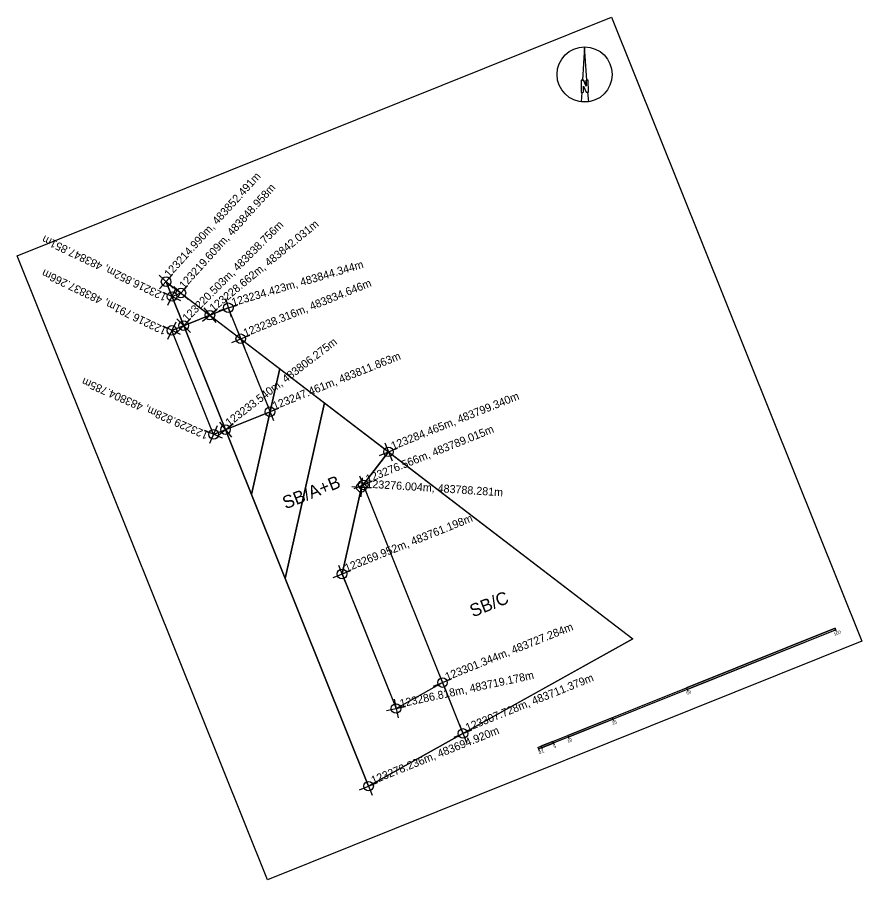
# Model space of a CAD drawing. Extents: x 123168 to 123432, y 483666 to 483935.
import ezdxf

# ---------------------------------------------------------------- set-up
doc = ezdxf.new("R2010")
doc.units = 0
for name, color, linetype in [('# coördinaten geheel', 7, 'Continuous'), ('# hulplijn', 7, 'Continuous'), ('Default', 7, 'Continuous')]:
    doc.layers.add(name, color=color, linetype=linetype)

msp = doc.modelspace()

# ---------------------------------------------------------------- linework, layer by layer
at = {"layer": '# coördinaten geheel'}
for p, q in [((123345.34, 483915.42), (123344.64, 483915.41)), ((123344.64, 483915.41), (123344.68, 483911.62)), ((123346.21, 483913.6), (123345.34, 483915.42)), ((123346.89, 483915.44), (123346.19, 483915.43)), ((123346.19, 483915.43), (123346.21, 483913.6)), ((123346.93, 483911.64), (123346.89, 483915.44)), ((123345.38, 483911.63), (123345.36, 483913.59)), ((123345.36, 483913.59), (123346.23, 483911.64)), ((123344.68, 483911.62), (123345.38, 483911.63)), ((123346.23, 483911.64), (123346.93, 483911.64)), ((123212.77, 483854.51), (123217.21, 483850.47)), ((123212.97, 483850.27), (123217.01, 483854.71)), ((123217.39, 483850.97), (123221.83, 483846.94)), ((123217.59, 483846.74), (123221.63, 483851.18)), ((123219.56, 483846.55), (123214.15, 483849.15)), ((123215.55, 483845.15), (123218.15, 483850.55)), ((123233.58, 483847.22), (123235.27, 483841.47)), ((123226.34, 483840.13), (123230.98, 483843.93)), ((123226.76, 483844.35), (123230.56, 483839.71)), ((123231.55, 483843.5), (123237.3, 483845.19)), ((123215.49, 483834.56), (123218.09, 483839.97)), ((123218.38, 483840.88), (123222.62, 483836.63)), ((123218.38, 483836.64), (123222.63, 483840.87)), ((123219.49, 483835.96), (123214.09, 483838.57)), ((123237.2, 483837.43), (123239.43, 483831.86)), ((123235.53, 483833.53), (123241.1, 483835.76)), ((123244.68, 483810.75), (123250.24, 483812.98)), ((123246.34, 483814.65), (123248.58, 483809.08)), ((123228.62, 483802.04), (123231.04, 483807.53)), ((123231.16, 483804.45), (123235.92, 483808.1)), ((123231.71, 483808.66), (123235.37, 483803.89)), ((123232.57, 483803.58), (123227.08, 483805.99)), ((123283.35, 483802.12), (123285.58, 483796.56)), ((123281.68, 483798.22), (123287.25, 483800.46)), ((123275.45, 483791.8), (123277.68, 483786.23)), ((123273.78, 483787.9), (123279.35, 483790.13)), ((123276.2, 483791.27), (123275.81, 483785.29)), ((123276.57, 483789.01), (123276.05, 483788.34)), ((123276.57, 483789.01), (123307.73, 483711.38)), ((123269.95, 483761.2), (123276, 483788.28)), ((123273.01, 483788.47), (123279, 483788.09)), ((123267.17, 483760.08), (123272.74, 483762.32)), ((123268.83, 483763.98), (123271.07, 483758.41)), ((123269.97, 483761.15), (123286.82, 483719.18)), ((123331.16, 483707), (123423.97, 483744.25)), ((123331.35, 483706.53), (123424.15, 483743.78)), ((123423.97, 483744.25), (123377.56, 483725.62)), ((123377.75, 483725.16), (123424.15, 483743.78)), ((123423.97, 483744.25), (123424.15, 483743.78)), ((123424.15, 483743.78), (123423.97, 483744.25)), ((123424.15, 483743.78), (123424.34, 483743.32)), ((123300.23, 483730.07), (123302.46, 483724.5)), ((123286.82, 483719.18), (123301.34, 483727.28)), ((123298.56, 483726.17), (123304.13, 483728.4)), ((123377.56, 483725.62), (123377.75, 483725.16)), ((123377.56, 483725.62), (123377.75, 483725.16)), ((123377.75, 483725.16), (123377.94, 483724.69)), ((123286.19, 483722.11), (123287.45, 483716.25)), ((123283.89, 483718.55), (123289.75, 483719.81)), ((123354.36, 483716.31), (123340.44, 483710.72)), ((123354.36, 483716.31), (123354.55, 483715.84)), ((123354.55, 483715.84), (123354.36, 483716.31)), ((123306.61, 483714.16), (123308.85, 483708.6)), ((123340.63, 483710.26), (123354.55, 483715.84)), ((123354.55, 483715.84), (123354.74, 483715.38)), ((123304.94, 483710.26), (123310.51, 483712.5)), ((123340.44, 483710.72), (123340.63, 483710.26)), ((123340.44, 483710.72), (123340.63, 483710.26)), ((123335.8, 483708.86), (123332.09, 483707.37)), ((123332.28, 483706.9), (123335.99, 483708.39)), ((123335.8, 483708.86), (123335.99, 483708.39)), ((123335.99, 483708.39), (123335.8, 483708.86)), ((123335.99, 483708.39), (123336.18, 483707.93)), ((123340.63, 483710.26), (123340.82, 483709.79)), ((123331.16, 483707), (123331.35, 483706.53)), ((123331.35, 483706.53), (123331.54, 483706.07)), ((123332.09, 483707.37), (123332.28, 483706.9)), ((123332.09, 483707.37), (123332.28, 483706.9)), ((123332.28, 483706.9), (123332.46, 483706.44)), ((123277.12, 483697.7), (123279.35, 483692.14)), ((123275.45, 483693.8), (123281.02, 483696.04))]:
    msp.add_line(p, q, dxfattribs=at)
for points in [[(123168.48, 483860.58), (123354.09, 483935.08), (123432.31, 483740.19), (123246.71, 483665.69)], [(123278.24, 483694.92), (123278.24, 483694.92), (123278.24, 483694.92), (123214.99, 483852.49), (123360.76, 483740.97)], [(123278.24, 483694.92), (123214.99, 483852.49), (123214.99, 483852.49), (123284.47, 483799.34), (123276.57, 483789.01), (123276, 483788.28), (123269.95, 483761.2), (123286.82, 483719.18), (123301.34, 483727.28), (123307.73, 483711.38)], [(123229.83, 483804.79), (123216.79, 483837.27), (123234.42, 483844.34), (123247.46, 483811.86)]]:
    msp.add_lwpolyline(points, close=True, dxfattribs=at)
for points in [[(123346.47, 483915.43), (123345.65, 483925.81), (123345.06, 483915.42)], [(123345.06, 483915.42), (123345.34, 483915.42), (123346.21, 483913.6), (123346.19, 483915.43), (123346.47, 483915.43)], [(123344.96, 483911.62), (123345.38, 483911.63), (123345.36, 483913.59), (123346.23, 483911.64), (123346.65, 483911.64)], [(123346.65, 483911.64), (123346.96, 483908.7), (123344.71, 483908.67), (123344.96, 483911.62)]]:
    msp.add_lwpolyline(points, dxfattribs=at)
for centre, radius in [((123345.73, 483917.2), 8.61), ((123214.99, 483852.49), 1.5), ((123216.85, 483847.85), 1.5), ((123219.61, 483848.96), 1.5), ((123234.42, 483844.34), 1.5), ((123228.66, 483842.03), 1.5), ((123220.5, 483838.76), 1.5), ((123216.79, 483837.27), 1.5), ((123238.32, 483834.65), 1.5), ((123247.46, 483811.86), 1.5), ((123233.54, 483806.28), 1.5), ((123229.83, 483804.79), 1.5), ((123284.47, 483799.34), 1.5), ((123276, 483788.28), 1.5), ((123276.57, 483789.01), 1.5), ((123269.95, 483761.2), 1.5), ((123301.34, 483727.28), 1.5), ((123286.82, 483719.18), 1.5), ((123307.73, 483711.38), 1.5), ((123278.24, 483694.92), 1.5)]:
    msp.add_circle(centre, radius, dxfattribs=at)
at = {"layer": '# hulplijn'}
for p, q in [((123214.99, 483852.49), (123278.24, 483694.92)), ((123214.99, 483852.49), (123284.37, 483799.42)), ((123216.85, 483847.85), (123219.61, 483848.96)), ((123234.42, 483844.34), (123216.79, 483837.27)), ((123234.42, 483844.34), (123247.46, 483811.86)), ((123229.83, 483804.79), (123216.79, 483837.27)), ((123250.47, 483825.34), (123241.68, 483786)), ((123264.47, 483814.63), (123252.21, 483759.76)), ((123229.83, 483804.79), (123247.46, 483811.86)), ((123284.37, 483799.42), (123360.76, 483740.97)), ((123276.57, 483789.01), (123284.47, 483799.34)), ((123276.57, 483789.01), (123307.73, 483711.38)), ((123307.73, 483711.38), (123360.76, 483740.97)), ((123278.24, 483694.92), (123307.73, 483711.38))]:
    msp.add_line(p, q, dxfattribs=at)
at = {"layer": 'Default'}
for p, q in [((123241.68, 483786), (123250.47, 483825.34)), ((123252.21, 483759.76), (123264.47, 483814.63))]:
    msp.add_line(p, q, dxfattribs=at)

# ---------------------------------------------------------------- texts
at = {"layer": '# coördinaten geheel'}
for s, height, rotation, p in [('123214.990m, 483852.491m', 2.5, 47.7571, (123216, 483853.6)), ('123219.609m, 483848.958m', 2.5, 47.7571, (123220.62, 483850.07)), ('123220.503m, 483838.756m', 2.5, 44.9156, (123221.57, 483839.82)), ('123228.662m, 483842.031m', 2.5, 39.314, (123229.82, 483842.98)), ('123216.852m, 483847.851m', 2.5, 154.2921, (123215.5, 483848.5)), ('123216.791m, 483837.266m', 2.5, 154.2921, (123215.44, 483837.92)), ('123234.423m, 483844.344m', 2.5, 16.3974, (123235.86, 483844.77)), ('123238.316m, 483834.646m', 2.5, 21.8698, (123239.71, 483835.2)), ('123233.540m, 483806.275m', 2.5, 37.4974, (123234.73, 483807.19)), ('123247.461m, 483811.863m', 2.5, 21.8698, (123248.85, 483812.42)), ('123229.828m, 483804.785m', 2.5, 156.2534, (123228.46, 483805.39)), ('123284.465m, 483799.340m', 2.5, 21.8698, (123285.86, 483799.9)), ('123276.566m, 483789.015m', 2.5, 21.8698, (123277.96, 483789.57)), ('123276.004m, 483788.281m', 2.5, 356.3219, (123277.5, 483788.18)), ('123269.952m, 483761.198m', 2.5, 21.8698, (123271.34, 483761.76)), ('123301.344m, 483727.284m', 2.5, 21.8698, (123302.74, 483727.84)), ('100', 1, 22.1698, (123423.77, 483741.85)), ('123286.818m, 483719.178m', 2.5, 12.145, (123288.28, 483719.49)), ('123307.728m, 483711.379m', 2.5, 21.8698, (123309.12, 483711.94)), ('50', 1, 22.1698, (123377.76, 483723.39)), ('25', 1, 22.1698, (123354.49, 483714.04)), ('123278.236m, 483694.920m', 2.5, 21.8698, (123279.63, 483695.48)), ('5', 1, 22.1698, (123336.23, 483706.72)), ('10', 1, 22.1698, (123340.55, 483708.45)), ('0', 1, 22.1698, (123331.63, 483704.87)), ('1', 1, 22.1698, (123332.48, 483705.21))]:
    msp.add_text(s, height=height, rotation=rotation, dxfattribs=at).set_placement(p)
at = {"layer": 'Default'}
for s, p in [('SB/A+B', (123252.33, 483781.36)), ('SB/C', (123310.83, 483747.61))]:
    msp.add_text(s, height=4, rotation=21.8698, dxfattribs=at).set_placement(p)

doc.saveas('drawing.dxf')
